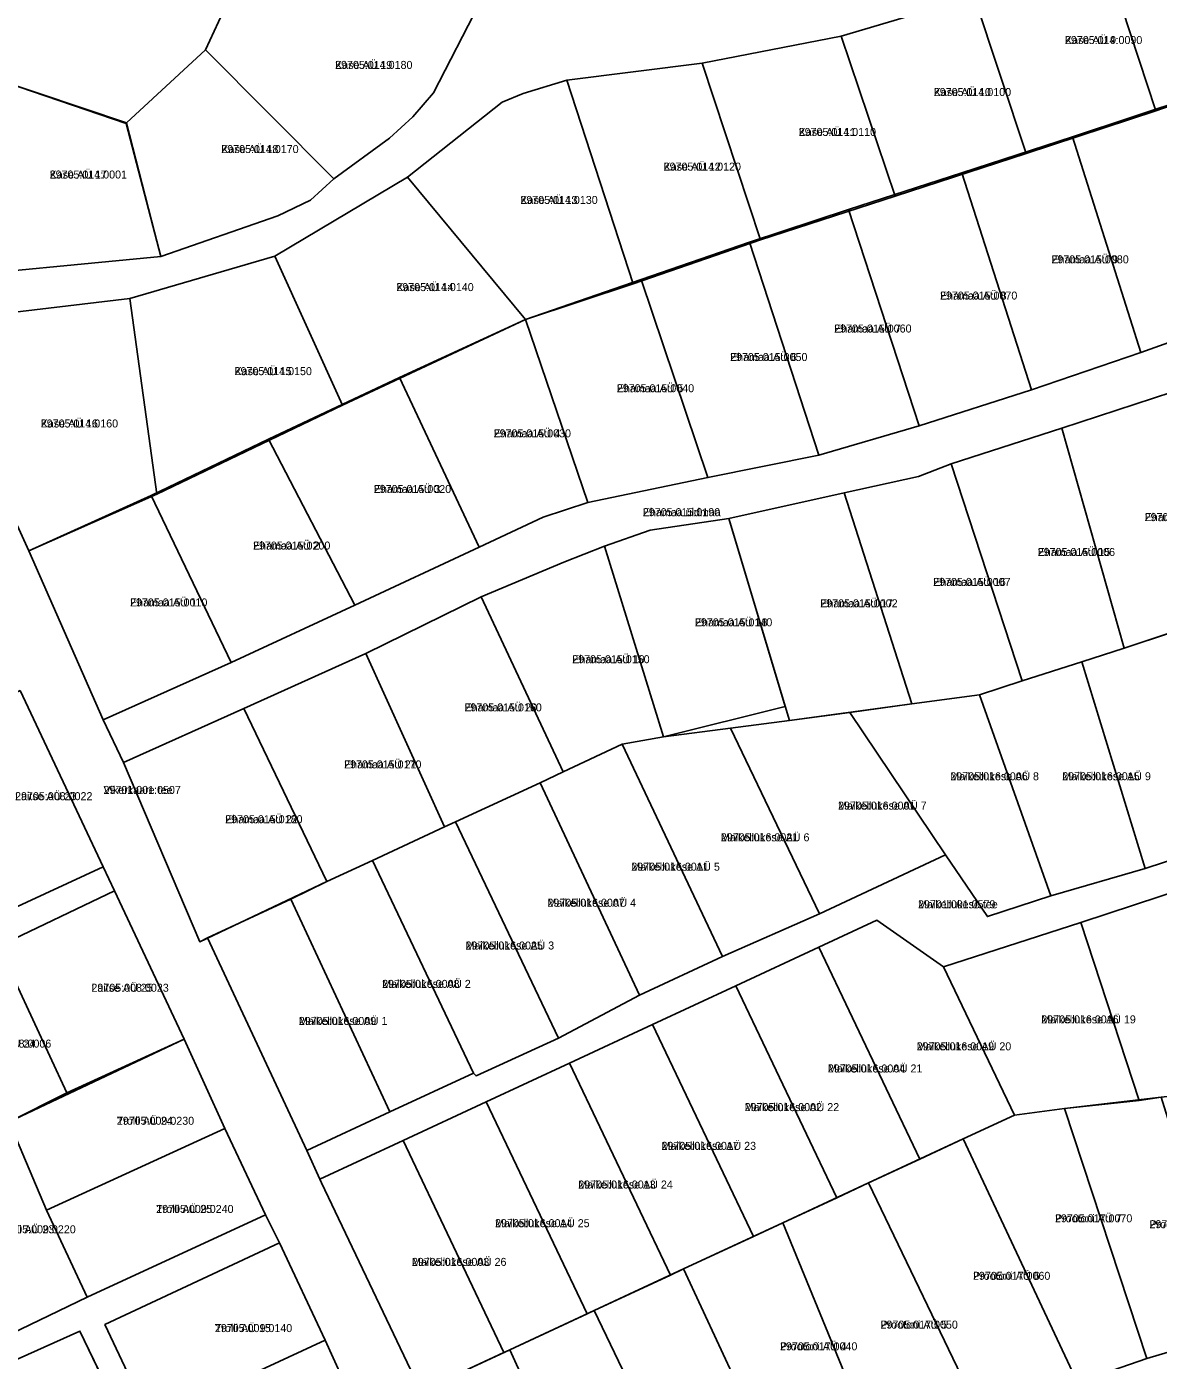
# Model space of a CAD drawing. Extents: x 504287 to 537970, y 6539941 to 6586214.
# Drawn here: x 519273.8 to 519486, y 6563035.9 to 6563285.9 of the extents above; entities that cross this region are included whole.
import ezdxf

# ---------------------------------------------------------------- set-up
doc = ezdxf.new("R2010")
doc.units = 0
for name, color, linetype in [('L_AADRESS', 7, 'Continuous'), ('PIIR', 7, 'Continuous'), ('TUNNUS', 7, 'Continuous')]:
    doc.layers.add(name, color=color, linetype=linetype)

msp = doc.modelspace()

# ---------------------------------------------------------------- linework, layer by layer
at = {"layer": 'PIIR'}
for points in [[(519499.82, 6563316.19), (519474.38, 6563303.98), (519451.48, 6563291.56), (519426.55, 6563284.12), (519400.49, 6563279.08), (519375.08, 6563275.85), (519366.92, 6563273.4), (519362.95, 6563271.76), (519345.22, 6563257.69), (519320.37, 6563242.86), (519293.15, 6563234.92), (519254.72, 6563230.35)], [(519254.76, 6563238.59), (519299.01, 6563242.84), (519320.92, 6563250.42), (519327.06, 6563253.35), (519331.44, 6563257.39), (519341.87, 6563265), (519346.23, 6563268.99), (519350.08, 6563273.49), (519358.81, 6563290.37)], [(519254.72, 6563230.35), (519274.24, 6563187.6), (519288.2, 6563155.95), (519291.97, 6563147.96), (519306.29, 6563114.35), (519307.76, 6563115.04), (519326.36, 6563075.17), (519328.8, 6563069.8), (519329.09, 6563069.16), (519347.72, 6563030.07)], [(519488.52, 6563217.41), (519467.92, 6563210.61), (519447.17, 6563203.93), (519441.02, 6563201.56), (519427.12, 6563198.48), (519405.47, 6563193.7), (519390.73, 6563191.49), (519382.19, 6563188.52), (519374.52, 6563185.48), (519359.02, 6563178.98), (519337.4, 6563168.41), (519314.52, 6563158.08), (519291.97, 6563147.96), (519288.2, 6563155.95), (519312.17, 6563166.67), (519335.37, 6563177.44), (519358.67, 6563188.33), (519370.67, 6563193.94), (519379.04, 6563196.72), (519401.57, 6563201.38), (519422.38, 6563205.58), (519441.15, 6563211.04), (519462.2, 6563217.8), (519482.74, 6563224.81), (519504.11, 6563232.45)], [(519336.76, 6563024.33), (519329.79, 6563039.66), (519321.26, 6563057.86), (519318.61, 6563063.16), (519311.01, 6563079.31), (519303.36, 6563096.05), (519290.29, 6563123.9), (519288.16, 6563128.39), (519272.6, 6563161.46)], [(519491.4, 6563124.51), (519471.45, 6563117.96), (519445.72, 6563109.62), (519433.25, 6563118.38), (519422.37, 6563113.32), (519406.78, 6563106.07), (519391.18, 6563098.81), (519375.59, 6563091.56), (519359.99, 6563084.31), (519344.4, 6563077.05), (519328.8, 6563069.8), (519326.36, 6563075.17), (519341.95, 6563082.45), (519357.62, 6563089.68), (519358.09, 6563089.18), (519373.55, 6563096.23), (519388.7, 6563104.29), (519404.28, 6563111.57), (519422.47, 6563119.54), (519446.08, 6563130.66), (519453.95, 6563119.07), (519465.83, 6563122.95), (519483.53, 6563128.06), (519501.12, 6563133.85)], [(519267.25, 6563039.05), (519285.2, 6563047.67), (519318.61, 6563063.16), (519321.26, 6563057.86), (519288.49, 6563042.57), (519297.06, 6563024.45), (519300.23, 6563018.09), (519295.89, 6563016.27), (519283.83, 6563041.33), (519256.32, 6563029.03)]]:
    msp.add_lwpolyline(points, dxfattribs=at)
for points in [[(519474.38, 6563303.98), (519499.82, 6563316.19), (519511.52, 6563279.21), (519485.51, 6563270.1)], [(519314.69, 6563297.36), (519307.34, 6563281.57), (519292.55, 6563267.85), (519267.39, 6563276.29), (519278.22, 6563309.66)], [(519451.48, 6563291.56), (519474.38, 6563303.98), (519485.51, 6563270.1), (519461.25, 6563262.14)], [(519314.69, 6563297.36), (519331.41, 6563291.91), (519333.66, 6563298.58), (519358.81, 6563290.37), (519350.08, 6563273.49), (519346.23, 6563268.99), (519341.87, 6563265), (519331.44, 6563257.39), (519307.34, 6563281.57)], [(519426.55, 6563284.12), (519451.48, 6563291.56), (519461.25, 6563262.14), (519436.64, 6563254.15)], [(519400.49, 6563279.08), (519426.55, 6563284.12), (519436.64, 6563254.15), (519411.43, 6563245.94)], [(519292.55, 6563267.85), (519307.34, 6563281.57), (519331.44, 6563257.39), (519327.06, 6563253.35), (519320.92, 6563250.42), (519299.01, 6563242.84)], [(519375.08, 6563275.85), (519400.49, 6563279.08), (519411.43, 6563245.94), (519387.57, 6563237.71)], [(519267.39, 6563276.29), (519292.51, 6563267.78), (519299.01, 6563242.84), (519254.76, 6563238.59)], [(519362.95, 6563271.76), (519366.92, 6563273.4), (519375.08, 6563275.85), (519387.57, 6563237.71), (519367.37, 6563230.99), (519345.22, 6563257.69)], [(519469.89, 6563265.27), (519492.51, 6563272.77), (519504.11, 6563232.45), (519482.74, 6563224.81)], [(519449.16, 6563258.51), (519469.89, 6563265.27), (519482.74, 6563224.81), (519462.2, 6563217.8)], [(519320.37, 6563242.86), (519345.22, 6563257.69), (519367.37, 6563230.99), (519333.04, 6563214.96)], [(519427.92, 6563251.6), (519449.16, 6563258.51), (519462.2, 6563217.8), (519441.15, 6563211.04)], [(519409.32, 6563245.48), (519427.92, 6563251.6), (519441.15, 6563211.04), (519422.38, 6563205.58)], [(519389.03, 6563238.48), (519409.32, 6563245.48), (519422.38, 6563205.58), (519401.57, 6563201.38)], [(519293.15, 6563234.92), (519320.37, 6563242.86), (519333.04, 6563214.96), (519298.22, 6563198.28)], [(519367.37, 6563230.99), (519389.03, 6563238.48), (519401.57, 6563201.38), (519379.04, 6563196.72)], [(519293.15, 6563234.92), (519298.22, 6563198.28), (519274.24, 6563187.6), (519254.72, 6563230.35)], [(519343.71, 6563220.1), (519367.37, 6563230.99), (519379.04, 6563196.72), (519370.67, 6563193.94), (519358.67, 6563188.33)], [(519319.15, 6563208.54), (519343.71, 6563220.1), (519358.67, 6563188.33), (519335.37, 6563177.44)], [(519467.92, 6563210.61), (519488.52, 6563217.41), (519498.93, 6563175.82), (519479.59, 6563169.4)], [(519447.17, 6563203.93), (519467.92, 6563210.61), (519479.59, 6563169.4), (519471.65, 6563166.84), (519460.46, 6563163.24)], [(519297.17, 6563198.03), (519319.15, 6563208.54), (519335.37, 6563177.44), (519312.17, 6563166.67)], [(519427.12, 6563198.48), (519441.02, 6563201.56), (519447.17, 6563203.93), (519460.46, 6563163.24), (519452.45, 6563160.66), (519439.78, 6563158.93)], [(519274.24, 6563187.6), (519297.17, 6563198.03), (519312.17, 6563166.67), (519288.2, 6563155.95)], [(519405.47, 6563193.7), (519427.12, 6563198.48), (519439.78, 6563158.93), (519416.84, 6563155.81)], [(519382.19, 6563188.52), (519390.73, 6563191.49), (519405.47, 6563193.7), (519416.05, 6563158.44), (519393.22, 6563152.74)], [(519359.02, 6563178.98), (519374.52, 6563185.48), (519382.19, 6563188.52), (519393.22, 6563152.74), (519385.5, 6563151.36), (519374.42, 6563146.21)], [(519337.4, 6563168.41), (519359.02, 6563178.98), (519374.42, 6563146.21), (519370.09, 6563144.16), (519354.24, 6563136.83), (519352.16, 6563135.86)], [(519471.65, 6563166.84), (519479.59, 6563169.4), (519488.44, 6563172.34), (519501.12, 6563133.85), (519483.53, 6563128.06)], [(519314.52, 6563158.08), (519337.4, 6563168.41), (519352.16, 6563135.86), (519338.67, 6563129.59), (519330.14, 6563125.62)], [(519471.65, 6563166.84), (519483.53, 6563128.06), (519465.83, 6563122.95), (519452.45, 6563160.66), (519460.46, 6563163.24)], [(519272.6, 6563161.46), (519288.16, 6563128.39), (519270.5, 6563120.2), (519255.16, 6563153.31)], [(519452.45, 6563160.66), (519465.83, 6563122.95), (519453.95, 6563119.07), (519446.08, 6563130.66), (519428.18, 6563157.35), (519439.78, 6563158.93)], [(519291.97, 6563147.96), (519314.52, 6563158.08), (519330.14, 6563125.62), (519306.29, 6563114.35)], [(519428.18, 6563157.35), (519446.08, 6563130.66), (519422.47, 6563119.54), (519405.82, 6563154.38), (519416.84, 6563155.81)], [(519405.82, 6563154.38), (519422.47, 6563119.54), (519404.28, 6563111.57), (519385.5, 6563151.36), (519393.22, 6563152.74)], [(519385.5, 6563151.36), (519404.28, 6563111.57), (519388.7, 6563104.29), (519370.09, 6563144.16), (519374.42, 6563146.21)], [(519370.09, 6563144.16), (519388.7, 6563104.29), (519373.55, 6563096.23), (519354.24, 6563136.83)], [(519338.67, 6563129.59), (519352.16, 6563135.86), (519354.24, 6563136.83), (519373.55, 6563096.23), (519358.09, 6563089.18), (519357.62, 6563089.68)], [(519096, 6563042.14), (519127.46, 6563056.78), (519152.61, 6563068.49), (519178.63, 6563080.61), (519182.36, 6563082.92), (519206.52, 6563094.02), (519207.64, 6563091.66), (519230.31, 6563101.3), (519234.52, 6563103.51), (519251.54, 6563111.41), (519270.5, 6563120.2), (519288.16, 6563128.39), (519290.29, 6563123.9), (519268.58, 6563113.51), (519246.55, 6563103.14), (519224.95, 6563093.03), (519203.18, 6563082.38), (519181.39, 6563072.35), (519180.43, 6563074.34), (519159.78, 6563064.8), (519139.13, 6563055.2), (519118.54, 6563046.17), (519098.11, 6563037)], [(519338.67, 6563129.59), (519357.62, 6563089.68), (519341.95, 6563082.45), (519323.34, 6563122.32), (519330.14, 6563125.62)], [(519268.58, 6563113.51), (519290.29, 6563123.9), (519303.36, 6563096.05), (519281.35, 6563085.98)], [(519491.4, 6563124.51), (519503.23, 6563087.06), (519486.52, 6563085.17), (519482.38, 6563084.6), (519471.45, 6563117.96)], [(519323.34, 6563122.32), (519341.95, 6563082.45), (519326.36, 6563075.17), (519307.76, 6563115.04)], [(519433.25, 6563118.38), (519445.72, 6563109.62), (519459.04, 6563081.85), (519449.42, 6563077.37), (519441.29, 6563073.59), (519422.37, 6563113.32)], [(519471.45, 6563117.96), (519482.38, 6563084.6), (519468.39, 6563083.05), (519459.04, 6563081.85), (519445.72, 6563109.62)], [(519268.58, 6563113.51), (519281.35, 6563085.98), (519270.53, 6563080.6), (519259.77, 6563075.79), (519246.55, 6563103.14)], [(519422.37, 6563113.32), (519441.29, 6563073.59), (519431.67, 6563069.12), (519425.7, 6563066.34), (519406.78, 6563106.07)], [(519406.78, 6563106.07), (519425.7, 6563066.34), (519415.6, 6563061.64), (519410.1, 6563059.09), (519391.18, 6563098.81)], [(519391.18, 6563098.81), (519410.1, 6563059.09), (519396.97, 6563052.98), (519394.51, 6563051.83), (519375.59, 6563091.56)], [(519270.53, 6563080.6), (519303.36, 6563096.05), (519311.01, 6563079.31), (519277.56, 6563063.99)], [(519375.59, 6563091.56), (519394.51, 6563051.83), (519380.21, 6563045.18), (519378.91, 6563044.58), (519359.99, 6563084.31)], [(519486.52, 6563085.17), (519500.29, 6563041.06), (519483.82, 6563036.19), (519468.39, 6563083.05)], [(519359.99, 6563084.31), (519378.91, 6563044.58), (519364.4, 6563037.83), (519363.32, 6563037.32), (519344.4, 6563077.05)], [(519459.04, 6563081.85), (519468.39, 6563083.05), (519483.82, 6563036.19), (519470.82, 6563031.67), (519449.42, 6563077.37)], [(519251.86, 6563071.99), (519270.53, 6563080.6), (519277.56, 6563063.99), (519285.2, 6563047.67), (519267.25, 6563039.05)], [(519277.56, 6563063.99), (519311.01, 6563079.31), (519318.61, 6563063.16), (519285.2, 6563047.67)], [(519344.4, 6563077.05), (519363.32, 6563037.32), (519347.72, 6563030.07), (519329.09, 6563069.16), (519328.8, 6563069.8)], [(519449.42, 6563077.37), (519470.82, 6563031.67), (519452.23, 6563026.37), (519431.67, 6563069.12)], [(519415.6, 6563061.64), (519431.67, 6563069.12), (519452.23, 6563026.37), (519433.17, 6563018.85)], [(519415.6, 6563061.64), (519433.17, 6563018.85), (519416.85, 6563010.23), (519396.97, 6563052.98)], [(519288.49, 6563042.57), (519321.26, 6563057.86), (519329.79, 6563039.66), (519297.06, 6563024.45)], [(519396.97, 6563052.98), (519416.85, 6563010.23), (519400.83, 6563002.24), (519380.21, 6563045.18)], [(519380.21, 6563045.18), (519400.83, 6563002.24), (519384.54, 6562993.66), (519364.4, 6563037.83)], [(519379.09, 6562978.83), (519372.84, 6562987.83), (519384.54, 6562993.66), (519400.83, 6563002.24), (519416.85, 6563010.23), (519433.17, 6563018.85), (519452.23, 6563026.37), (519470.82, 6563031.67), (519483.82, 6563036.19), (519500.29, 6563041.06), (519518.28, 6563044.73), (519537.55, 6563044.73), (519555.2, 6563044.87), (519572.77, 6563044.98), (519588.48, 6563045.08), (519591.71, 6563035.32), (519563.15, 6563035.15), (519540.86, 6563035.52), (519516.8, 6563034.6), (519500.02, 6563030.32), (519441.15, 6563010.5), (519419.88, 6562999.55), (519403.66, 6562991.39), (519386.67, 6562982.83)], [(519256.88, 6563027.76), (519256.32, 6563029.03), (519283.83, 6563041.33), (519294.48, 6563019.19), (519266.68, 6563005.97)], [(519300.23, 6563018.09), (519297.06, 6563024.45), (519329.79, 6563039.66), (519336.76, 6563024.33), (519306.55, 6563004.35)], [(519364.4, 6563037.83), (519384.54, 6562993.66), (519372.84, 6562987.83), (519369.94, 6562989.02), (519366.85, 6562990.32), (519347.72, 6563030.07)]]:
    msp.add_lwpolyline(points, close=True, dxfattribs=at)

# ---------------------------------------------------------------- texts
at = {"layer": 'L_AADRESS'}
for s, p in [('Kase AÜ 9', (519468.49, 6563282.65)), ('Kase AÜ 19', (519331.66, 6563277.99)), ('Kase AÜ 10', (519443.9, 6563272.9)), ('Kase AÜ 11', (519418.57, 6563265.42)), ('Kase AÜ 18', (519310.32, 6563262.21)), ('Kase AÜ 12', (519393.25, 6563258.92)), ('Kase AÜ 17', (519278.14, 6563257.44)), ('Kase AÜ 13', (519366.39, 6563252.67)), ('Ehamaa AÜ 9', (519465.95, 6563241.53)), ('Kase AÜ 14', (519343.14, 6563236.33)), ('Ehamaa AÜ 8', (519445.06, 6563234.74)), ('Ehamaa AÜ 7', (519425.23, 6563228.56)), ('Ehamaa AÜ 6', (519405.71, 6563223.22)), ('Kase AÜ 15', (519312.81, 6563220.57)), ('Ehamaa AÜ 5', (519384.47, 6563217.37)), ('Kase AÜ 16', (519276.47, 6563210.76)), ('Ehamaa AÜ 4', (519361.38, 6563208.91)), ('Ehamaa AÜ 3', (519338.91, 6563198.47)), ('Ehamaa üldmaa', (519389.35, 6563194.13)), ('Ehamaa AÜ 14', (519483.43, 6563193.2)), ('Ehamaa AÜ 2', (519316.27, 6563187.87)), ('Ehamaa AÜ 15', (519463.38, 6563186.66)), ('Ehamaa AÜ 16', (519443.79, 6563181.05)), ('Ehamaa AÜ 1', (519293.21, 6563177.21)), ('Ehamaa AÜ 17', (519422.62, 6563177.04)), ('Ehamaa AÜ 18', (519399.12, 6563173.48)), ('Ehamaa AÜ 19', (519376.12, 6563166.56)), ('Ehamaa AÜ 20', (519355.91, 6563157.53)), ('Ehamaa AÜ 21', (519333.34, 6563146.84)), ('Maikellukese AÜ 8', (519447, 6563144.61)), ('Maikellukese AÜ 9', (519467.99, 6563144.62)), ('Laitse AÜ 23', (519271.66, 6563140.88)), ('Vikerkaare tee', (519288.24, 6563142.05)), ('Maikellukese AÜ 7', (519425.95, 6563139.11)), ('Ehamaa AÜ 22', (519311.05, 6563136.56)), ('Maikellukese AÜ 6', (519403.98, 6563133.17)), ('Maikellukese AÜ 5', (519387.19, 6563127.66)), ('Maikellukese AÜ 4', (519371.47, 6563120.9)), ('Maikellukese tee', (519440.95, 6563120.61)), ('Maikellukese AÜ 3', (519356.11, 6563112.88)), ('Maikellukese AÜ 2', (519340.48, 6563105.69)), ('Laitse AÜ 25', (519285.97, 6563104.96)), ('Maikellukese AÜ 1', (519324.86, 6563098.74)), ('Maikellukese AÜ 19', (519464.05, 6563099.03)), ('Laitse AÜ 24', (519263.95, 6563094.49)), ('Maikellukese AÜ 20', (519440.7, 6563093.98)), ('Maikellukese AÜ 21', (519424.04, 6563089.83)), ('Maikellukese AÜ 22', (519408.44, 6563082.58)), ('Trolli AÜ 24', (519290.73, 6563080.02)), ('Maikellukese AÜ 23', (519392.85, 6563075.32)), ('Maikellukese AÜ 24', (519377.25, 6563068.07)), ('Trolli AÜ 25', (519298.12, 6563063.49)), ('Maikellukese AÜ 25', (519361.65, 6563060.82)), ('Prootoni AÜ 7', (519466.62, 6563061.73)), ('Prootoni AÜ 8', (519484.34, 6563060.63)), ('Trolli AÜ 23', (519268.53, 6563059.67)), ('Maikellukese AÜ 26', (519346.06, 6563053.56)), ('Prootoni AÜ 6', (519451.25, 6563050.95)), ('Trolli AÜ 15', (519309.12, 6563041.15)), ('Prootoni AÜ 5', (519433.91, 6563041.8)), ('Prootoni AÜ 4', (519415.07, 6563037.73))]:
    msp.add_text(s, height=1.5, dxfattribs=at).set_placement(p)
at = {"layer": 'TUNNUS'}
for s, p in [('29705:014:0090', (519468.49, 6563282.65)), ('29705:014:0180', (519331.66, 6563277.99)), ('29705:014:0100', (519443.9, 6563272.9)), ('29705:014:0110', (519418.57, 6563265.42)), ('29705:014:0170', (519310.32, 6563262.21)), ('29705:014:0120', (519393.25, 6563258.92)), ('29705:014:0001', (519278.14, 6563257.44)), ('29705:014:0130', (519366.39, 6563252.67)), ('29705:015:0080', (519465.95, 6563241.53)), ('29705:014:0140', (519343.14, 6563236.33)), ('29705:015:0070', (519445.06, 6563234.74)), ('29705:015:0060', (519425.23, 6563228.56)), ('29705:015:0050', (519405.71, 6563223.22)), ('29705:014:0150', (519312.81, 6563220.57)), ('29705:015:0040', (519384.47, 6563217.37)), ('29705:014:0160', (519276.47, 6563210.76)), ('29705:015:0030', (519361.38, 6563208.91)), ('29705:015:0020', (519338.91, 6563198.47)), ('29705:015:0190', (519389.35, 6563194.13)), ('29705:015:0005', (519483.43, 6563193.2)), ('29705:015:0200', (519316.27, 6563187.87)), ('29705:015:0006', (519463.38, 6563186.66)), ('29705:015:0007', (519443.79, 6563181.05)), ('29705:015:0010', (519293.21, 6563177.21)), ('29705:015:0002', (519422.62, 6563177.04)), ('29705:015:0140', (519399.12, 6563173.48)), ('29705:015:0150', (519376.12, 6563166.56)), ('29705:015:0160', (519355.91, 6563157.53)), ('29705:015:0170', (519333.34, 6563146.84)), ('29705:016:0006', (519447, 6563144.61)), ('29705:016:0015', (519467.99, 6563144.62)), ('29701:001:0507', (519288.24, 6563142.05)), ('29705:008:0022', (519271.66, 6563140.88)), ('29705:016:0001', (519425.95, 6563139.11)), ('29705:015:0180', (519311.05, 6563136.56)), ('29705:016:0021', (519403.98, 6563133.17)), ('29705:016:0011', (519387.19, 6563127.66)), ('29705:016:0007', (519371.47, 6563120.9)), ('29701:001:0579', (519440.95, 6563120.61)), ('29705:016:0025', (519356.11, 6563112.88)), ('29705:008:0023', (519285.97, 6563104.96)), ('29705:016:0008', (519340.48, 6563105.69)), ('29705:016:0009', (519324.86, 6563098.74)), ('29705:016:0016', (519464.05, 6563099.03)), ('29705:008:0006', (519263.95, 6563094.49)), ('29705:016:0019', (519440.7, 6563093.98)), ('29705:016:0004', (519424.04, 6563089.83)), ('29705:016:0002', (519408.44, 6563082.58)), ('29705:009:0230', (519290.73, 6563080.02)), ('29705:016:0017', (519392.85, 6563075.32)), ('29705:016:0013', (519377.25, 6563068.07)), ('29705:009:0240', (519298.12, 6563063.49)), ('29705:017:0070', (519466.62, 6563061.73)), ('29705:009:0220', (519268.53, 6563059.67)), ('29705:016:0014', (519361.65, 6563060.82)), ('29705:017:0130', (519484.34, 6563060.63)), ('29705:016:0003', (519346.06, 6563053.56)), ('29705:017:0060', (519451.25, 6563050.95)), ('29705:009:0140', (519309.12, 6563041.15)), ('29705:017:0050', (519433.91, 6563041.8)), ('29705:017:0040', (519415.07, 6563037.73))]:
    msp.add_text(s, height=1.5, dxfattribs=at).set_placement(p)

doc.saveas('drawing.dxf')
